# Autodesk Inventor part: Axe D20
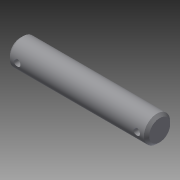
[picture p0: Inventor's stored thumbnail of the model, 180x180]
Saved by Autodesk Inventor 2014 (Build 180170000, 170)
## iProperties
Created: 2015-09
Part Number: Axe D20
Material: Générique
Document SubType Name: Modeling
Designer: OL
Density: 1 g/cm^3
Appearance: Par défaut
Author: OL
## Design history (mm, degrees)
sketch "Esquisse1"
  geometry: C1 r 10 at (0, 0); 1 further point
  constraints: 1 centre point, 1 coincident
  dimensions: "d0" = 20 diameter of C1
extrude "Extrusion1" new body sketch "Esquisse1" distance "d2" = 106; taper "d3" = 0 deg
chamfer "Chanfrein1" distance "d4" = 2; stored, may be unused: second distance "d5" = 2, angle "d6" = 45 deg
sketch "Esquisse2"
  geometry: C1 r 2.5 at (-98.5, 0); C2 r 2.5 at (-7.5, 0); 1 further point
  constraints: 2 centre point
  dimensions: "d7" = 5 diameter of C1; "d9" = 5 diameter of C2; "d10" = 7.5 distance of point (0, 0) C2.centre; "d11" = 98.5 distance of point (0, 0) C1.centre
extrude "Extrusion2" cut sketch "Esquisse2" stored distance "d13" = 100; taper "d14" = 0 deg
node "Solide1"
